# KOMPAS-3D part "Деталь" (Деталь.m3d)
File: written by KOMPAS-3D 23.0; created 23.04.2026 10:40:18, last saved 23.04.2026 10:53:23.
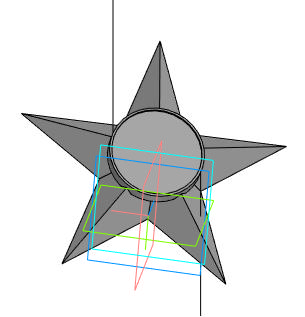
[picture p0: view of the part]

Document properties: Автор: USER; Полное имя файла: C:\Users\USER\Desktop\Деталь.m3d

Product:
- Part/product: Деталь
    Масса: 0.28486

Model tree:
1. Эскиз:1
2. Элемент выдавливания:1
     Расстояние 1 = 15; Угол 1 = -40
3. Смещенная плоскость:1
     Расстояние = 12
4. Эскиз:3  (with: Элемент выдавливания:1)
5. Элемент выдавливания:3
     Расстояние 1 = 6
6. Эскиз:4  (with: Элемент выдавливания:3)
7. Элемент выдавливания:4
     Расстояние 2 = 1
